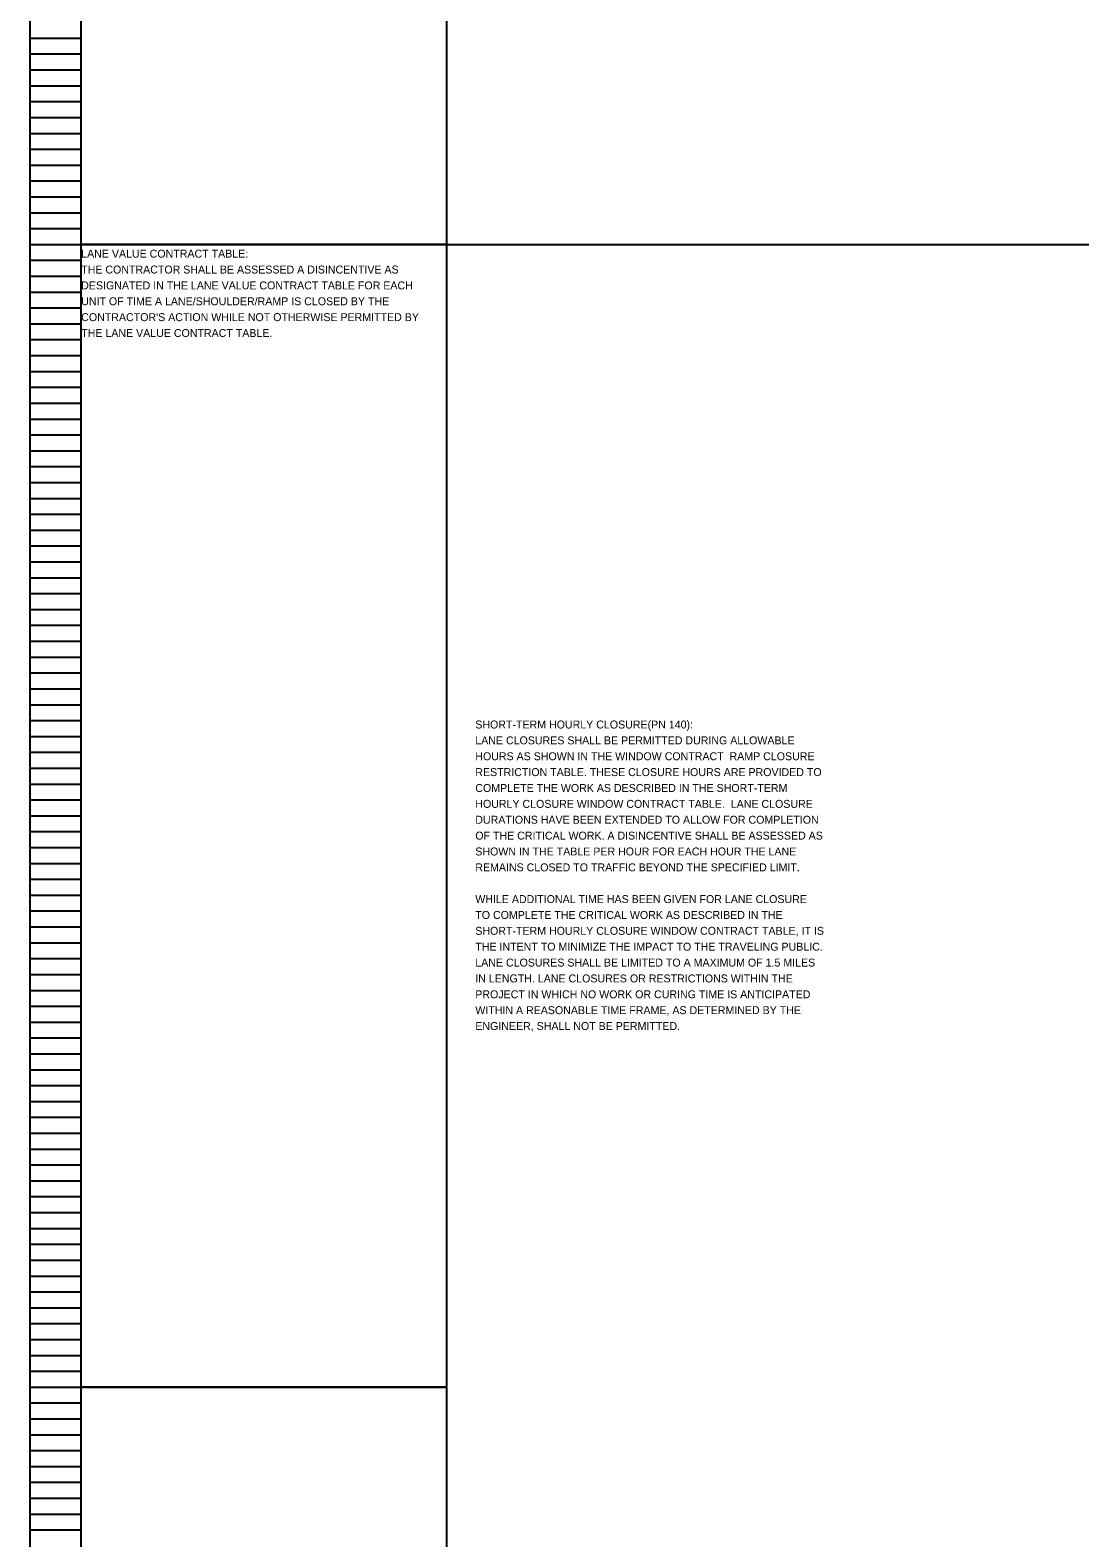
# Model space of a CAD drawing. Extents: x 16463 to 16500, y 5400 to 5823.
# Drawn here: x 16463.05 to 16481.55, y 5558.73 to 5585.33 of the extents above; entities that cross this region are included whole.
import ezdxf

# ---------------------------------------------------------------- set-up
doc = ezdxf.new("R2010")
doc.units = 0
for name, color, linetype in [('Default', 7, 'Continuous'), ('SC_Scratch1', 7, 'Continuous'), ('SH_Data', 7, 'Continuous'), ('SH_Text', 7, 'Continuous')]:
    doc.layers.add(name, color=color, linetype=linetype)

msp = doc.modelspace()

# ---------------------------------------------------------------- linework, layer by layer
at = {"layer": 'SC_Scratch1'}
msp.add_line((16470.389, 5581.552), (16500.06, 5581.552), dxfattribs=at)
for points in [[(16463.949, 5601.712), (16470.389, 5601.712), (16470.389, 5581.552), (16463.949, 5581.552)], [(16463.949, 5581.552), (16470.389, 5581.552), (16470.389, 5561.392), (16463.949, 5561.392)], [(16463.949, 5561.392), (16470.389, 5561.392), (16470.389, 5541.232), (16463.949, 5541.232)]]:
    msp.add_lwpolyline(points, close=True, dxfattribs=at)
at = {"layer": 'SH_Data'}
for p, q in [((16463.049, 5581.552), (16463.049, 5601.712)), ((16463.949, 5581.552), (16463.949, 5601.712)), ((16463.049, 5585.192), (16463.949, 5585.192)), ((16463.049, 5584.912), (16463.949, 5584.912)), ((16463.049, 5584.632), (16463.949, 5584.632)), ((16463.049, 5584.352), (16463.949, 5584.352)), ((16463.049, 5584.072), (16463.949, 5584.072)), ((16463.049, 5583.792), (16463.949, 5583.792)), ((16463.049, 5583.512), (16463.949, 5583.512)), ((16463.049, 5583.232), (16463.949, 5583.232)), ((16463.049, 5582.952), (16463.949, 5582.952)), ((16463.049, 5582.672), (16463.949, 5582.672)), ((16463.049, 5582.392), (16463.949, 5582.392)), ((16463.049, 5582.112), (16463.949, 5582.112)), ((16463.049, 5581.832), (16463.949, 5581.832)), ((16463.049, 5561.392), (16463.049, 5581.552)), ((16463.049, 5581.552), (16463.949, 5581.552)), ((16463.049, 5581.552), (16463.949, 5581.552)), ((16463.949, 5561.392), (16463.949, 5581.552)), ((16463.049, 5581.272), (16463.949, 5581.272)), ((16463.049, 5580.992), (16463.949, 5580.992)), ((16463.049, 5580.712), (16463.949, 5580.712)), ((16463.049, 5580.432), (16463.949, 5580.432)), ((16463.049, 5580.152), (16463.949, 5580.152)), ((16463.049, 5579.872), (16463.949, 5579.872)), ((16463.049, 5579.592), (16463.949, 5579.592)), ((16463.049, 5579.312), (16463.949, 5579.312)), ((16463.049, 5579.032), (16463.949, 5579.032)), ((16463.049, 5578.752), (16463.949, 5578.752)), ((16463.049, 5578.472), (16463.949, 5578.472)), ((16463.049, 5578.192), (16463.949, 5578.192)), ((16463.049, 5577.912), (16463.949, 5577.912)), ((16463.049, 5577.632), (16463.949, 5577.632)), ((16463.049, 5577.352), (16463.949, 5577.352)), ((16463.049, 5577.072), (16463.949, 5577.072)), ((16463.049, 5576.792), (16463.949, 5576.792)), ((16463.049, 5576.512), (16463.949, 5576.512)), ((16463.049, 5576.232), (16463.949, 5576.232)), ((16463.049, 5575.952), (16463.949, 5575.952)), ((16463.049, 5575.672), (16463.949, 5575.672)), ((16463.049, 5575.392), (16463.949, 5575.392)), ((16463.049, 5575.112), (16463.949, 5575.112)), ((16463.049, 5574.832), (16463.949, 5574.832)), ((16463.049, 5574.552), (16463.949, 5574.552)), ((16463.049, 5574.272), (16463.949, 5574.272)), ((16463.049, 5573.992), (16463.949, 5573.992)), ((16463.049, 5573.712), (16463.949, 5573.712)), ((16463.049, 5573.432), (16463.949, 5573.432)), ((16463.049, 5573.152), (16463.949, 5573.152)), ((16463.049, 5572.872), (16463.949, 5572.872)), ((16463.049, 5572.592), (16463.949, 5572.592)), ((16463.049, 5572.312), (16463.949, 5572.312)), ((16463.049, 5572.032), (16463.949, 5572.032)), ((16463.049, 5571.752), (16463.949, 5571.752)), ((16463.049, 5571.472), (16463.949, 5571.472)), ((16463.049, 5571.192), (16463.949, 5571.192)), ((16463.049, 5570.912), (16463.949, 5570.912)), ((16463.049, 5570.632), (16463.949, 5570.632)), ((16463.049, 5570.352), (16463.949, 5570.352)), ((16463.049, 5570.072), (16463.949, 5570.072)), ((16463.049, 5569.792), (16463.949, 5569.792)), ((16463.049, 5569.512), (16463.949, 5569.512)), ((16463.049, 5569.232), (16463.949, 5569.232)), ((16463.049, 5568.952), (16463.949, 5568.952)), ((16463.049, 5568.672), (16463.949, 5568.672)), ((16463.049, 5568.392), (16463.949, 5568.392)), ((16463.049, 5568.112), (16463.949, 5568.112)), ((16463.049, 5567.832), (16463.949, 5567.832)), ((16463.049, 5567.552), (16463.949, 5567.552)), ((16463.049, 5567.272), (16463.949, 5567.272)), ((16463.049, 5566.992), (16463.949, 5566.992)), ((16463.049, 5566.712), (16463.949, 5566.712)), ((16463.049, 5566.432), (16463.949, 5566.432)), ((16463.049, 5566.152), (16463.949, 5566.152)), ((16463.049, 5565.872), (16463.949, 5565.872)), ((16463.049, 5565.592), (16463.949, 5565.592)), ((16463.049, 5565.312), (16463.949, 5565.312)), ((16463.049, 5565.032), (16463.949, 5565.032)), ((16463.049, 5564.752), (16463.949, 5564.752)), ((16463.049, 5564.472), (16463.949, 5564.472)), ((16463.049, 5564.192), (16463.949, 5564.192)), ((16463.049, 5563.912), (16463.949, 5563.912)), ((16463.049, 5563.632), (16463.949, 5563.632)), ((16463.049, 5563.352), (16463.949, 5563.352)), ((16463.049, 5563.072), (16463.949, 5563.072)), ((16463.049, 5562.792), (16463.949, 5562.792)), ((16463.049, 5562.512), (16463.949, 5562.512)), ((16463.049, 5562.232), (16463.949, 5562.232)), ((16463.049, 5561.952), (16463.949, 5561.952)), ((16463.049, 5561.672), (16463.949, 5561.672)), ((16463.049, 5541.232), (16463.049, 5561.392)), ((16463.049, 5561.392), (16463.949, 5561.392)), ((16463.049, 5561.392), (16463.949, 5561.392)), ((16463.949, 5541.232), (16463.949, 5561.392)), ((16463.049, 5561.112), (16463.949, 5561.112)), ((16463.049, 5560.832), (16463.949, 5560.832)), ((16463.049, 5560.552), (16463.949, 5560.552)), ((16463.049, 5560.272), (16463.949, 5560.272)), ((16463.049, 5559.992), (16463.949, 5559.992)), ((16463.049, 5559.712), (16463.949, 5559.712)), ((16463.049, 5559.432), (16463.949, 5559.432)), ((16463.049, 5559.152), (16463.949, 5559.152)), ((16463.049, 5558.872), (16463.949, 5558.872))]:
    msp.add_line(p, q, dxfattribs=at)

# ---------------------------------------------------------------- texts
at = {"layer": 'Default'}
for s, p in [('LANE VALUE CONTRACT TABLE:', (16463.949, 5581.319)), ('THE CONTRACTOR SHALL BE ASSESSED A DISINCENTIVE AS ', (16463.949, 5581.039)), ('DESIGNATED IN THE LANE VALUE CONTRACT TABLE FOR EACH ', (16463.949, 5580.759)), ('UNIT OF TIME A LANE/SHOULDER/RAMP IS CLOSED BY THE ', (16463.949, 5580.479)), ("CONTRACTOR'S ACTION WHILE NOT OTHERWISE PERMITTED BY ", (16463.949, 5580.199)), ('THE LANE VALUE CONTRACT TABLE.', (16463.949, 5579.919))]:
    msp.add_text(s, height=0.14, dxfattribs=at).set_placement(p)
at = {"layer": 'SH_Text'}
for s, p in [('SHORT-TERM HOURLY CLOSURE(PN 140):', (16470.897, 5573.012)), ('LANE CLOSURES SHALL BE PERMITTED DURING ALLOWABLE ', (16470.897, 5572.732)), ('HOURS AS SHOWN IN THE WINDOW CONTRACT  RAMP CLOSURE ', (16470.897, 5572.452)), ('RESTRICTION TABLE. THESE CLOSURE HOURS ARE PROVIDED TO ', (16470.897, 5572.172)), ('COMPLETE THE WORK AS DESCRIBED IN THE SHORT-TERM ', (16470.897, 5571.892)), ('HOURLY CLOSURE WINDOW CONTRACT TABLE.  LANE CLOSURE ', (16470.897, 5571.612)), ('DURATIONS HAVE BEEN EXTENDED TO ALLOW FOR COMPLETION ', (16470.897, 5571.332)), ('OF THE CRITICAL WORK. A DISINCENTIVE SHALL BE ASSESSED AS ', (16470.897, 5571.052)), ('SHOWN IN THE TABLE PER HOUR FOR EACH HOUR THE LANE ', (16470.897, 5570.772)), ('REMAINS CLOSED TO TRAFFIC BEYOND THE SPECIFIED LIMIT.  ', (16470.897, 5570.492)), ('WHILE ADDITIONAL TIME HAS BEEN GIVEN FOR LANE CLOSURE ', (16470.897, 5569.932)), ('TO COMPLETE THE CRITICAL WORK AS DESCRIBED IN THE ', (16470.897, 5569.652)), ('SHORT-TERM HOURLY CLOSURE WINDOW CONTRACT TABLE, IT IS ', (16470.897, 5569.372)), ('THE INTENT TO MINIMIZE THE IMPACT TO THE TRAVELING PUBLIC. ', (16470.897, 5569.092)), ('LANE CLOSURES SHALL BE LIMITED TO A MAXIMUM OF 1.5 MILES ', (16470.897, 5568.812)), ('IN LENGTH. LANE CLOSURES OR RESTRICTIONS WITHIN THE ', (16470.897, 5568.532)), ('PROJECT IN WHICH NO WORK OR CURING TIME IS ANTICIPATED ', (16470.897, 5568.252)), ('WITHIN A REASONABLE TIME FRAME, AS DETERMINED BY THE ', (16470.897, 5567.972)), ('ENGINEER, SHALL NOT BE PERMITTED.', (16470.897, 5567.692))]:
    msp.add_text(s, height=0.14, dxfattribs=at).set_placement(p)

doc.saveas('drawing.dxf')
